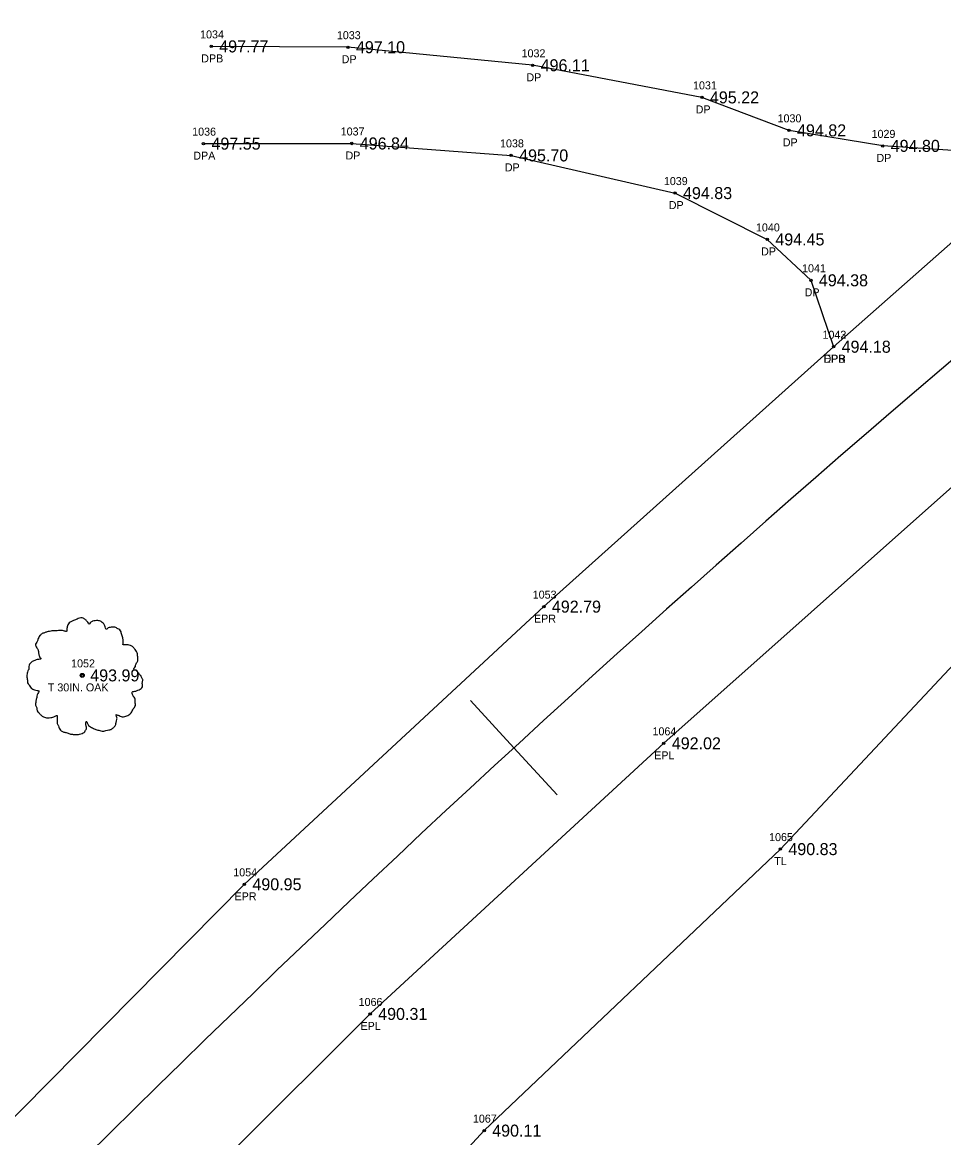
# Model space of a CAD drawing. Extents: x 1740701 to 1743138, y 748181 to 751839.
# Drawn here: x 1741947.8 to 1742062.9, y 750456.4 to 750595.8 of the extents above; entities that cross this region are included whole.
import ezdxf

# ---------------------------------------------------------------- set-up
doc = ezdxf.new("R2010")
doc.units = 0
for name, color, linetype in [('RD_EX_Driveway', 7, 'Continuous'), ('RD_EX_Driveway_txCode', 7, 'Continuous'), ('RD_EX_Road', 7, 'Continuous'), ('RD_EX_Road_txCode', 7, 'Continuous'), ('RD_EX_TX_Driveway_ELEV', 7, 'Continuous'), ('RD_EX_TX_Road_ELEV', 7, 'Continuous'), ('RD_EX_TX_VEG_ELEV', 7, 'Continuous'), ('RD_EX_VEG', 7, 'Continuous'), ('RD_EX_VEG_txCode', 7, 'Continuous'), ('RD_HC_Cl', 7, 'Continuous'), ('RD_HC_Data_Tic', 7, 'Continuous'), ('RD_SMD_Locator', 7, 'Continuous')]:
    doc.layers.add(name, color=color, linetype=linetype)

msp = doc.modelspace()

# ---------------------------------------------------------------- linework, layer by layer
at = {"layer": 'RD_EX_Driveway'}
for points in [[(1742078.23, 750580.89), (1742067.75, 750579.5), (1742055.26, 750580.31), (1742043.56, 750582.25), (1742032.68, 750586.37), (1742011.54, 750590.38), (1741988.47, 750592.64), (1741971.4, 750592.74)], [(1741970.43, 750580.59), (1741988.95, 750580.61), (1742008.85, 750579.12), (1742029.32, 750574.41), (1742040.85, 750568.62), (1742046.29, 750563.51), (1742049.13, 750555.21)]]:
    msp.add_lwpolyline(points, dxfattribs=at)
at = {"layer": 'RD_EX_Road'}
for points in [[(1742095.24, 750593.27), (1742088.27, 750587.97), (1742078.23, 750580.89), (1742049.13, 750555.21), (1742012.94, 750522.73), (1741975.54, 750488.03), (1741940.71, 750452.82), (1741916.22, 750428.67), (1741904.72, 750416.99), (1741884.38, 750395.02), (1741870.75, 750380.27), (1741817.36, 750322.98), (1741803.89, 750307.66), (1741783.86, 750287.33), (1741735.44, 750234.07), (1741718.84, 750214.98), (1741710.25, 750205.58), (1741668.97, 750159.8), (1741635, 750122.49), (1741604.35, 750087.7), (1741600.63, 750085.47)], [(1742102.43, 750570.61), (1742093.26, 750562.71), (1742064.72, 750538.42), (1742027.92, 750505.65), (1741991.25, 750471.83), (1741956.32, 750436.98), (1741921.43, 750401.39), (1741886.79, 750364.93), (1741819.64, 750292.67), (1741751.78, 750219.01), (1741684.42, 750145.59), (1741650.98, 750108.5), (1741637.17, 750092.42), (1741621.17, 750073.94), (1741621.31, 750072.22), (1741619.24, 750070.27)]]:
    msp.add_lwpolyline(points, dxfattribs=at)
at = {"layer": 'RD_EX_VEG'}
msp.add_lwpolyline([(1742114.37, 750556.95), (1742102.57, 750548.5), (1742074.74, 750526.88), (1742042.48, 750492.43), (1742005.49, 750457.25), (1741971.49, 750420.27), (1741936.96, 750386.65), (1741902.94, 750350.76), (1741835.15, 750278.46), (1741766.69, 750206.43), (1741693.82, 750135.64), (1741661.95, 750096.11), (1741631.51, 750044.18), (1741602.3, 750028.04), (1741573.25, 749982.32), (1741544.84, 749941.06), (1741514.68, 749901.47), (1741495.89, 749858.02), (1741462.75, 749819.18), (1741434.73, 749775.9), (1741408.39, 749735.06), (1741355.53, 749651.67)], dxfattribs=at)
for centre, radius in [((1741955.29, 750514.14), 0.25), ((1741955.28, 750514.12), 0.0001)]:
    msp.add_circle(centre, radius, dxfattribs=at)
for points in [[(1741955.42, 750521.31), (1741955.12, 750521.33), (1741954.79, 750521.23), (1741954.54, 750521.13), (1741954.32, 750521.06), (1741954.1, 750520.96), (1741953.8, 750520.78), (1741953.57, 750520.58), (1741953.45, 750520.33), (1741953.4, 750520.11), (1741953.35, 750519.84), (1741953.35, 750519.66), (1741953.22, 750519.64), (1741953.07, 750519.66), (1741952.82, 750519.74), (1741952.57, 750519.74), (1741952.32, 750519.74), (1741951.97, 750519.71), (1741951.62, 750519.71), (1741951.35, 750519.66), (1741951.02, 750519.61), (1741950.65, 750519.49), (1741950.3, 750519.36), (1741950, 750519.11), (1741949.75, 750518.64), (1741949.62, 750518.29), (1741949.47, 750518.04), (1741949.62, 750517.59), (1741949.8, 750517.24), (1741949.82, 750517.04), (1741949.9, 750516.61), (1741950, 750516.39), (1741950.12, 750516.19), (1741950.05, 750516.16), (1741949.67, 750516.11), (1741949.37, 750516.01), (1741948.95, 750515.79), (1741948.72, 750515.56), (1741948.62, 750515.24), (1741948.6, 750514.89), (1741948.5, 750514.69), (1741948.42, 750514.41), (1741948.4, 750514.34), (1741948.35, 750514.01), (1741948.45, 750513.56), (1741948.47, 750513.21), (1741948.6, 750512.99), (1741948.75, 750512.81), (1741948.92, 750512.56), (1741949.32, 750512.34), (1741949.65, 750512.24), (1741949.85, 750512.21), (1741949.67, 750511.71), (1741949.62, 750511.36), (1741949.5, 750510.96), (1741949.5, 750510.89), (1741949.45, 750510.41), (1741949.6, 750510.09), (1741949.67, 750509.71), (1741949.85, 750509.49), (1741950.12, 750509.19), (1741950.45, 750508.96), (1741950.95, 750508.84), (1741951.35, 750508.86), (1741951.92, 750509.04), (1741952.17, 750509.11), (1741952.15, 750508.94), (1741952.17, 750508.56), (1741952.17, 750508.14), (1741952.32, 750507.82), (1741952.42, 750507.54), (1741952.57, 750507.29), (1741952.9, 750507.07), (1741953.3, 750506.99), (1741953.72, 750506.84), (1741954.17, 750506.77), (1741954.67, 750506.74), (1741955.27, 750506.89), (1741955.54, 750507.02), (1741955.64, 750507.19), (1741955.84, 750507.57), (1741955.79, 750507.79), (1741955.82, 750508.39), (1741955.92, 750508.22), (1741956.09, 750507.87), (1741956.59, 750507.57), (1741956.99, 750507.39), (1741957.47, 750507.24), (1741957.77, 750507.17), (1741958.24, 750507.24), (1741958.62, 750507.32), (1741958.99, 750507.44), (1741959.29, 750507.72), (1741959.47, 750507.99), (1741959.52, 750508.27), (1741959.59, 750508.64), (1741959.64, 750508.81)], [(1741959.64, 750508.81), (1741959.57, 750508.99), (1741959.52, 750509.24), (1741959.59, 750509.21), (1741959.77, 750509.16), (1741960.04, 750509.04), (1741960.27, 750508.96), (1741960.59, 750508.99), (1741960.87, 750509.09), (1741961.32, 750509.36), (1741961.59, 750509.84), (1741961.87, 750510.24), (1741961.94, 750510.56), (1741961.89, 750510.79), (1741961.87, 750511.29), (1741961.67, 750511.54), (1741961.62, 750511.66), (1741961.52, 750512.06), (1741961.59, 750512.11), (1741961.87, 750512.16), (1741962.24, 750512.29), (1741962.52, 750512.41), (1741962.74, 750512.59), (1741962.82, 750512.81), (1741962.79, 750513.21), (1741962.84, 750513.61), (1741962.77, 750513.76), (1741962.67, 750513.91), (1741962.59, 750514.11), (1741962.44, 750514.26), (1741962.34, 750514.41), (1741962.24, 750514.51), (1741962.12, 750514.66), (1741961.94, 750514.79), (1741961.79, 750514.84), (1741961.74, 750514.99), (1741961.89, 750515.19), (1741961.94, 750515.29), (1741961.97, 750515.51), (1741962.19, 750515.86), (1741962.24, 750516.26), (1741962.19, 750516.69), (1741962.14, 750516.96), (1741961.99, 750517.24), (1741961.79, 750517.49), (1741961.67, 750517.66), (1741961.49, 750517.79), (1741961.17, 750517.91), (1741960.92, 750517.96), (1741960.57, 750517.96), (1741960.37, 750518.01), (1741960.39, 750518.06), (1741960.39, 750518.21), (1741960.39, 750518.49), (1741960.32, 750518.94), (1741960.17, 750519.44), (1741960.17, 750519.46), (1741960.07, 750519.71), (1741959.84, 750519.91), (1741959.67, 750520.01), (1741959.47, 750520.13), (1741959.22, 750520.16), (1741958.92, 750520.16), (1741958.64, 750520.11), (1741958.44, 750520.01), (1741958.27, 750519.89), (1741958.19, 750520.03), (1741958.09, 750520.33), (1741958.04, 750520.48), (1741957.89, 750520.66), (1741957.67, 750520.86), (1741957.22, 750520.98), (1741956.59, 750520.91), (1741956.29, 750520.71), (1741956.14, 750520.53), (1741956.09, 750520.66), (1741955.89, 750520.86), (1741955.79, 750521.03), (1741955.62, 750521.16), (1741955.47, 750521.26), (1741955.37, 750521.31)]]:
    msp.add_spline(points, degree=3, dxfattribs=at)
at = {"layer": 'RD_HC_Cl'}
msp.add_arc((1743302.33, 749099.61), 1909.86, 121.38831, 137.32219, dxfattribs=at)
at = {"layer": 'RD_HC_Data_Tic'}
for q in [(1742003.79, 750510.99), (1742014.62, 750499.21)]:
    msp.add_line((1742009.21, 750505.1), q, dxfattribs=at)
at = {"layer": 'RD_SMD_Locator'}
for centre in [(1741971.4, 750592.74), (1741988.47, 750592.64), (1742011.54, 750590.38), (1742032.68, 750586.37), (1742043.56, 750582.25), (1741970.43, 750580.59), (1741988.95, 750580.61), (1742008.85, 750579.12), (1742055.26, 750580.31), (1742029.32, 750574.41), (1742040.85, 750568.62), (1742046.29, 750563.51), (1742049.13, 750555.21), (1742049.13, 750555.21), (1742012.94, 750522.73), (1741955.29, 750514.14), (1742027.92, 750505.65), (1742042.48, 750492.43), (1741975.54, 750488.03), (1741991.25, 750471.83), (1742005.49, 750457.25)]:
    msp.add_circle(centre, 0.15, dxfattribs=at)

# ---------------------------------------------------------------- texts
at = {"layer": 'RD_EX_Driveway_txCode'}
for s, p in [('1034', (1741970.01, 750593.74)), ('1033', (1741987.09, 750593.64)), ('1032', (1742010.16, 750591.38)), ('DPB', (1741970.15, 750590.74)), ('DP', (1741987.69, 750590.64)), ('DP', (1742010.76, 750588.38)), ('1031', (1742031.57, 750587.37)), ('DP', (1742031.9, 750584.37)), ('1030', (1742042.13, 750583.25)), ('1036', (1741969.02, 750581.59)), ('1037', (1741987.57, 750581.61)), ('1029', (1742053.87, 750581.31)), ('1038', (1742007.47, 750580.12)), ('DP', (1742042.78, 750580.25)), ('DPA', (1741969.16, 750578.59)), ('DP', (1741988.17, 750578.61)), ('DP', (1742054.48, 750578.31)), ('DP', (1742008.07, 750577.12)), ('1039', (1742027.93, 750575.41)), ('DP', (1742028.54, 750572.41)), ('1040', (1742039.43, 750569.62)), ('DP', (1742040.07, 750566.62)), ('1041', (1742045.19, 750564.51)), ('DP', (1742045.51, 750561.51)), ('1042', (1742047.74, 750556.21)), ('DPB', (1742047.87, 750553.21))]:
    msp.add_text(s, height=1, dxfattribs=at).set_placement(p)
at = {"layer": 'RD_EX_Road_txCode'}
for s, p in [('1043', (1742047.74, 750556.21)), ('EPR', (1742047.9, 750553.21)), ('1053', (1742011.55, 750523.73)), ('EPR', (1742011.71, 750520.73)), ('1064', (1742026.51, 750506.65)), ('EPL', (1742026.72, 750503.65)), ('1054', (1741974.15, 750489.03)), ('EPR', (1741974.31, 750486.03)), ('1066', (1741989.81, 750472.83)), ('EPL', (1741990.04, 750469.83))]:
    msp.add_text(s, height=1, dxfattribs=at).set_placement(p)
at = {"layer": 'RD_EX_TX_Driveway_ELEV'}
for s, p in [('497.77', (1741972.4, 750591.99)), ('497.10', (1741989.47, 750591.89)), ('496.11', (1742012.54, 750589.63)), ('495.22', (1742033.68, 750585.62)), ('494.82', (1742044.56, 750581.5)), ('497.55', (1741971.43, 750579.84)), ('496.84', (1741989.95, 750579.86)), ('494.80', (1742056.26, 750579.56)), ('495.70', (1742009.85, 750578.37)), ('494.83', (1742030.32, 750573.66)), ('494.45', (1742041.85, 750567.87)), ('494.38', (1742047.29, 750562.76)), ('494.18', (1742050.13, 750554.46))]:
    msp.add_text(s, height=1.5, dxfattribs=at).set_placement(p)
at = {"layer": 'RD_EX_TX_Road_ELEV'}
for s, p in [('494.18', (1742050.13, 750554.46)), ('492.79', (1742013.94, 750521.98)), ('492.02', (1742028.92, 750504.9)), ('490.95', (1741976.54, 750487.28)), ('490.31', (1741992.25, 750471.08))]:
    msp.add_text(s, height=1.5, dxfattribs=at).set_placement(p)
at = {"layer": 'RD_EX_TX_VEG_ELEV'}
for s, p in [('493.99', (1741956.29, 750513.39)), ('490.83', (1742043.48, 750491.68)), ('490.11', (1742006.49, 750456.5))]:
    msp.add_text(s, height=1.5, dxfattribs=at).set_placement(p)
at = {"layer": 'RD_EX_VEG_txCode'}
for s, p in [('1052', (1741953.9, 750515.14)), ('T 30IN. OAK', (1741950.99, 750512.14)), ('1065', (1742041.07, 750493.43)), ('TL', (1742041.71, 750490.43)), ('1067', (1742004.08, 750458.25))]:
    msp.add_text(s, height=1, dxfattribs=at).set_placement(p)

doc.saveas('drawing.dxf')
